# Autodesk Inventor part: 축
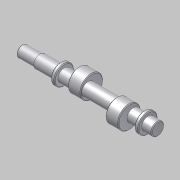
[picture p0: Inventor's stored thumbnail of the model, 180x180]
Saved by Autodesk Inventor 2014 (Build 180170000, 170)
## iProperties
Created: 2013-02
Part Number: 축
Document SubType Name: Modeling
Designer: 한국산업디자인학원[gmhk.co.kr]
Density: 1 g/cm^3
Material: 일반
Appearance: 기본값
Mass: 58.3378 g
Surface Area: 143.366 cm^2
Volume: 58.3378 cm^3
Author: 한국산업디자인학원[gmhk.co.kr]
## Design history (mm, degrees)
sketch "스케치2"
  geometry: L1 (-58, 84.5)-(-58, 15.5) reference; L2 (58, 15.5)-(58, 84.5) reference; L3 (-85, 25.774)-(-85, 74.226) reference; L4 (70, 84.185)-(70, 15.815) reference; L5 (71, 50)-(-109, 50); L6 (69.4, 58.5)-(58.6, 58.5) reference; L7 (71, 50)-(71, 58.5); L8 (71, 58.5)-(58, 58.5); L9 (58, 58.5)-(58, 63); L10 (58, 63)-(53, 63); L11 (53, 63)-(53, 58.5); L12 (53, 58.5)-(-53, 58.5); L13 (-53, 58.5)-(-53, 63); L14 (-53, 63)-(-58, 63); L15 (-58, 63)-(-58, 58.5); L16 (-58, 58.5)-(-85, 58.5); L17 (-85, 58.5)-(-85, 57.5); L18 (-85, 57.5)-(-109, 57.5); L19 (-109, 57.5)-(-109, 50); L20 (-30, 102.5)-(-30, 50); L21 (30, 102.5)-(30, 50); L22 (-50, 102.5)-(-10, 102.5) reference; L23 (10, 102.5)-(50, 102.5) reference; 2 further points
  constraints: 34 end point, 10 perpendicular, 9 point on line, 5 collinear, 3 midpoint, 3 parallel, 1 horizontal, 2 other
  dimensions: "d0" = 1 distance between parallel lines of L7 L4; "d1" = 26 diameter of L10 L5; "d2" = 5 distance of L9.end L10.end; "d3" = 5 distance of L13.end L14.end (= d2); "d4" = 180 distance of L5.start L5.end; "d5" = 15 diameter of L18 L5
  node "참조1"
  node "참조2"
  node "참조3"
  node "참조4"
  node "참조7"
  node "참조8"
revolve "회전1" stored, may be unused: angle "d6" = 90 deg
node "작업 평면1"
sketch "스케치3"
  geometry: C1 r 8.5 at (52.5, 0) reference; C2 r 15 at (47.5, 0); 1 further point
  constraints: 1 centre point, 1 horizontal alignment
  dimensions: "d8" = 5 distance of C1.centre C2.centre; "d9" = 30 diameter of C2
extrude "돌출1" join sketch "스케치3" stored distance "d10" = 17; taper "d11" = 0 deg
node "작업 평면2"
sketch "스케치4"
  geometry: C1 r 8.5 at (52.5, 0) reference; C2 r 15 at (57.5, 0); 1 further point
  constraints: 1 centre point, 1 horizontal alignment
  dimensions: "d13" = 5 distance of C2.centre C1.centre; "d14" = 30 diameter of C2
extrude "돌출2" join sketch "스케치4" stored distance "d15" = 17; taper "d16" = 0 deg
chamfer "모따기1" distance "d17" = 1; stored, may be unused: second distance "d18" = 2, angle "d19" = 45 deg
node "작업 평면3"
sketch "스케치5"
  geometry: L1 (12, 6.5)-(12, -6.5) reference; L2 (12, 2.5)-(-5.5, 2.5); L3 (-5.5, -2.5)-(12, -2.5); A1 r 2.5 centre (-5.5, 0) between (-5.5, 2.5) and (-5.5, -2.5); 2 further points
  constraints: 4 end point, 2 point on circle, 2 point on line, 2 tangent, 1 centre point, 1 horizontal alignment, 1 midpoint, 1 parallel, 1 perpendicular
  dimensions: "d20" = 5 distance between parallel lines of L3 L2; "d21" = 20 dimension on A1 L1
extrude "돌출3" cut sketch "스케치5" distance "d22" = 3; taper "d23" = 0 deg
chamfer "모따기2" distance "d24" = 1; stored, may be unused: second distance "d25" = 2, angle "d26" = 45 deg
node "솔리드1"
node "투영된 루프1"
node "투영된 루프2"
other parameters: "d7" = 0, "d12" = 0
